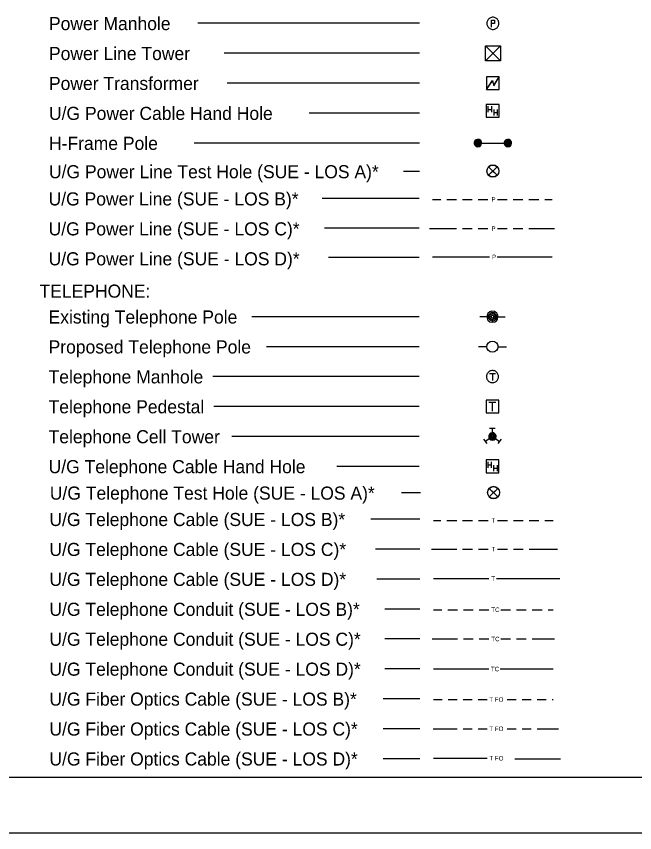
# Model space of a CAD drawing. Extents: x 2040834 to 2047174, y 618431 to 621625.
# Drawn here: x 2046085 to 2046571, y 620341 to 620983 of the extents above; entities that cross this region are included whole.
import ezdxf

# ---------------------------------------------------------------- set-up
doc = ezdxf.new("R2010")
doc.units = 0
for name, color, linetype in [('Default', 7, 'Continuous'), ('Exist Utilities Power Test Hole SUE LOS A CELL', 7, 'Continuous'), ('Exist Utilities Telephone Test Hole SUE LOS A CELL', 7, 'Continuous')]:
    doc.layers.add(name, color=color, linetype=linetype)

msp = doc.modelspace()

# ---------------------------------------------------------------- linework, layer by layer
at = {"layer": 'Default'}
for p, q in [((2046401.89, 620977.7), (2046227.49, 620977.7)), ((2046460.53, 620977.47), (2046458.39, 620977.47)), ((2046460.92, 620979.88), (2046460.92, 620977.85)), ((2046465.49, 620960.07), (2046453.73, 620948.31)), ((2046465.49, 620948.31), (2046453.73, 620960.07)), ((2046401.89, 620954.16), (2046248.08, 620954.16)), ((2046401.89, 620930.62), (2046250.46, 620930.62)), ((2046455.72, 620912.48), (2046455.72, 620907.74)), ((2046458.43, 620912.48), (2046458.43, 620907.74)), ((2046401.89, 620907.07), (2046314.91, 620907.07)), ((2046455.72, 620910.06), (2046458.43, 620910.06)), ((2046460.25, 620909.89), (2046460.25, 620905.15)), ((2046460.25, 620907.48), (2046462.96, 620907.48)), ((2046462.96, 620909.89), (2046462.96, 620905.15)), ((2046401.89, 620883.53), (2046224.51, 620883.53)), ((2046447.81, 620883.53), (2046471.35, 620883.53)), ((2046401.89, 620861.2), (2046389.37, 620861.2)), ((2046401.56, 620839.81), (2046325.15, 620839.81)), ((2046412.17, 620839.23), (2046418.65, 620839.23)), ((2046423.35, 620839.23), (2046431.01, 620839.23)), ((2046435.71, 620839.23), (2046443.37, 620839.23)), ((2046448.07, 620839.23), (2046455.72, 620839.23)), ((2046463.26, 620839.23), (2046470.91, 620839.23)), ((2046475.62, 620839.23), (2046483.27, 620839.23)), ((2046487.98, 620839.23), (2046495.63, 620839.23)), ((2046500.34, 620839.23), (2046506.34, 620839.23)), ((2046401.56, 620816.72), (2046326.96, 620816.72)), ((2046409.79, 620816.27), (2046431.01, 620816.27)), ((2046435.71, 620816.27), (2046443.37, 620816.27)), ((2046448.07, 620816.27), (2046455.72, 620816.27)), ((2046463.26, 620816.27), (2046470.91, 620816.27)), ((2046475.62, 620816.27), (2046483.27, 620816.27)), ((2046487.98, 620816.27), (2046508.02, 620816.27)), ((2046401.56, 620793.63), (2046330.13, 620793.63)), ((2046412.17, 620793.95), (2046457, 620793.95)), ((2046462.89, 620793.95), (2046506.34, 620793.95)), ((2046401.56, 620746.95), (2046269.86, 620746.95)), ((2046454.91, 620746.95), (2046449.26, 620746.95)), ((2046463.6, 620746.95), (2046469.25, 620746.95)), ((2046401.56, 620723.41), (2046281.43, 620723.41)), ((2046454.89, 620723.4), (2046448.27, 620723.4)), ((2046463.71, 620723.4), (2046470.34, 620723.4)), ((2046401.56, 620699.87), (2046239.29, 620699.87)), ((2046461.7, 620702.09), (2046456.85, 620702.09)), ((2046459.26, 620702.09), (2046459.26, 620696.74)), ((2046401.56, 620676.33), (2046240.11, 620676.33)), ((2046456.5, 620679.88), (2046462.01, 620679.88)), ((2046459.26, 620672.78), (2046459.26, 620679.88)), ((2046457.05, 620659.45), (2046461.46, 620659.45)), ((2046459.26, 620655.68), (2046459.26, 620659.45)), ((2046401.56, 620652.79), (2046254.16, 620652.79)), ((2046455.07, 620647.16), (2046452.54, 620650.78)), ((2046456.89, 620651.13), (2046453.81, 620648.97)), ((2046461.63, 620651.13), (2046464.71, 620648.97)), ((2046465.98, 620650.78), (2046463.45, 620647.17)), ((2046401.56, 620629.24), (2046336.78, 620629.24)), ((2046455.65, 620632.81), (2046455.65, 620628.06)), ((2046455.65, 620630.39), (2046458.36, 620630.39)), ((2046458.36, 620632.81), (2046458.36, 620628.06)), ((2046460.18, 620630.22), (2046460.18, 620625.48)), ((2046462.89, 620630.22), (2046462.89, 620625.48)), ((2046460.18, 620627.81), (2046462.89, 620627.81)), ((2046402.53, 620608.44), (2046387.63, 620608.44)), ((2046402.21, 620587.7), (2046363.62, 620587.7)), ((2046412.82, 620586.76), (2046418.73, 620586.76)), ((2046423.44, 620586.76), (2046431.09, 620586.76)), ((2046435.8, 620586.76), (2046443.45, 620586.76)), ((2046448.16, 620586.76), (2046455.81, 620586.76)), ((2046463.34, 620586.76), (2046470.99, 620586.76)), ((2046475.7, 620586.76), (2046483.35, 620586.76)), ((2046488.06, 620586.76), (2046495.71, 620586.76)), ((2046500.42, 620586.76), (2046506.98, 620586.76)), ((2046402.21, 620564.15), (2046367.34, 620564.15)), ((2046411.34, 620564.15), (2046431.09, 620564.15)), ((2046435.8, 620564.15), (2046443.45, 620564.15)), ((2046448.16, 620564.15), (2046455.81, 620564.15)), ((2046463.34, 620564.15), (2046470.99, 620564.15)), ((2046475.7, 620564.15), (2046483.35, 620564.15)), ((2046488.06, 620564.15), (2046510.47, 620564.15)), ((2046402.21, 620540.61), (2046368.24, 620540.61)), ((2046412.82, 620541.02), (2046456.51, 620541.02)), ((2046462.4, 620541.02), (2046512.28, 620541.02)), ((2046402.21, 620517.07), (2046374.59, 620517.07)), ((2046412.82, 620516.57), (2046419.39, 620516.57)), ((2046424.1, 620516.57), (2046431.75, 620516.57)), ((2046436.46, 620516.57), (2046444.11, 620516.57)), ((2046448.82, 620516.57), (2046456.47, 620516.57)), ((2046465.89, 620516.57), (2046473.54, 620516.57)), ((2046478.25, 620516.57), (2046485.9, 620516.57)), ((2046490.61, 620516.57), (2046498.26, 620516.57)), ((2046502.97, 620516.57), (2046506.98, 620516.57)), ((2046402.21, 620493.53), (2046374.59, 620493.53)), ((2046411.7, 620493.53), (2046431.75, 620493.53)), ((2046436.46, 620493.53), (2046444.11, 620493.53)), ((2046448.82, 620493.53), (2046456.47, 620493.53)), ((2046465.89, 620493.53), (2046473.54, 620493.53)), ((2046478.25, 620493.53), (2046485.9, 620493.53)), ((2046490.61, 620493.53), (2046508.11, 620493.53)), ((2046402.21, 620469.99), (2046374.59, 620469.99)), ((2046412.82, 620469.93), (2046456.47, 620469.93)), ((2046465.3, 620469.93), (2046506.98, 620469.93)), ((2046402.21, 620446.44), (2046373.22, 620446.44)), ((2046412.82, 620445.93), (2046419.69, 620445.93)), ((2046424.39, 620445.93), (2046431.46, 620445.93)), ((2046436.17, 620445.93), (2046443.23, 620445.93)), ((2046447.94, 620445.93), (2046455, 620445.93)), ((2046470.89, 620445.93), (2046477.95, 620445.93)), ((2046482.66, 620445.93), (2046489.72, 620445.93)), ((2046494.43, 620445.93), (2046501.49, 620445.93)), ((2046506.2, 620445.93), (2046506.98, 620445.93)), ((2046402.21, 620422.9), (2046373.22, 620422.9)), ((2046412.6, 620422.9), (2046431.46, 620422.9)), ((2046436.17, 620422.9), (2046443.23, 620422.9)), ((2046447.94, 620422.9), (2046455, 620422.9)), ((2046470.89, 620422.9), (2046477.95, 620422.9)), ((2046482.66, 620422.9), (2046489.72, 620422.9)), ((2046494.43, 620422.9), (2046511.28, 620422.9)), ((2046402.21, 620399.36), (2046373.22, 620399.36)), ((2046412.82, 620399.75), (2046455.04, 620399.75)), ((2046476.82, 620399.29), (2046512.87, 620399.29)), ((2045118.13, 620384.96), (2047013.93, 620384.96)), ((2045074.38, 620341.21), (2047057.71, 620341.21))]:
    msp.add_line(p, q, dxfattribs=at)
for points in [[(2046459.58, 620982.48), (2046458.97, 620982.44), (2046458.39, 620982.33), (2046457.82, 620982.13), (2046457.28, 620981.87), (2046456.79, 620981.56), (2046456.33, 620981.18), (2046455.91, 620980.72), (2046455.56, 620980.26), (2046455.26, 620979.73), (2046455.07, 620979.15), (2046454.91, 620978.58), (2046454.84, 620978.01), (2046454.84, 620977.39), (2046454.91, 620976.82), (2046455.07, 620976.21), (2046455.26, 620975.67), (2046455.56, 620975.14), (2046455.91, 620974.68), (2046456.33, 620974.22), (2046456.79, 620973.84), (2046457.28, 620973.53), (2046457.82, 620973.26), (2046458.39, 620973.07), (2046459, 620972.96), (2046459.58, 620972.92), (2046460.19, 620972.96), (2046460.76, 620973.07), (2046461.34, 620973.26), (2046461.87, 620973.53), (2046462.37, 620973.84), (2046462.83, 620974.22), (2046463.25, 620974.68), (2046463.59, 620975.14), (2046463.9, 620975.67), (2046464.09, 620976.25), (2046464.24, 620976.82), (2046464.32, 620977.39), (2046464.32, 620978.01), (2046464.24, 620978.58), (2046464.09, 620979.19), (2046463.9, 620979.73), (2046463.59, 620980.26), (2046463.25, 620980.72), (2046462.83, 620981.18), (2046462.37, 620981.56), (2046461.87, 620981.87), (2046461.34, 620982.13), (2046460.76, 620982.33), (2046460.15, 620982.44), (2046459.58, 620982.48)], [(2046458.39, 620974.64), (2046458.39, 620977.47), (2046458.39, 620980.26), (2046460.53, 620980.26)], [(2046460.53, 620980.26), (2046460.69, 620980.22), (2046460.8, 620980.15), (2046460.88, 620980.03), (2046460.92, 620979.88)], [(2046460.92, 620977.85), (2046460.88, 620977.7), (2046460.8, 620977.58), (2046460.69, 620977.51), (2046460.53, 620977.47)], [(2046465.49, 620948.31), (2046453.73, 620948.31), (2046453.73, 620960.07), (2046465.49, 620960.07), (2046465.49, 620948.31), (2046453.73, 620948.31), (2046453.73, 620960.07), (2046465.49, 620960.07), (2046465.49, 620948.31)], [(2046454.67, 620925.71), (2046459.3, 620932.37), (2046460.43, 620928.75), (2046464.48, 620935.52)], [(2046454.67, 620925.71), (2046459.34, 620932.64), (2046460.39, 620928.47), (2046464.48, 620935.52)], [(2046454.67, 620925.71), (2046464.48, 620925.71), (2046464.48, 620935.52), (2046454.67, 620935.52), (2046454.67, 620925.71)], [(2046454.27, 620903.85), (2046464.4, 620903.85), (2046464.4, 620913.98), (2046454.27, 620913.98), (2046454.27, 620903.85)], [(2046449.95, 620883.53), (2046449.89, 620884.05), (2046449.72, 620884.52), (2046449.43, 620884.92), (2046449.08, 620885.27), (2046448.68, 620885.5), (2046448.15, 620885.62), (2046447.69, 620885.68), (2046447.17, 620885.56), (2046446.71, 620885.39), (2046446.36, 620885.1), (2046446.01, 620884.69), (2046445.78, 620884.28), (2046445.66, 620883.76), (2046445.66, 620883.3), (2046445.78, 620882.78), (2046446.01, 620882.37), (2046446.36, 620881.97), (2046446.71, 620881.68), (2046447.17, 620881.5), (2046447.69, 620881.39), (2046448.15, 620881.45), (2046448.68, 620881.56), (2046449.08, 620881.8), (2046449.43, 620882.14), (2046449.72, 620882.55), (2046449.89, 620883.01), (2046449.95, 620883.53)], [(2046449.25, 620883.53), (2046449.2, 620883.94), (2046449.02, 620884.34), (2046448.73, 620884.63), (2046448.39, 620884.86), (2046448.04, 620884.98), (2046447.57, 620884.98), (2046447.23, 620884.86), (2046446.88, 620884.63), (2046446.59, 620884.34), (2046446.42, 620883.94), (2046446.36, 620883.53), (2046446.42, 620883.13), (2046446.59, 620882.72), (2046446.88, 620882.43), (2046447.23, 620882.2), (2046447.57, 620882.08), (2046448.04, 620882.08), (2046448.39, 620882.2), (2046448.73, 620882.43), (2046449.02, 620882.72), (2046449.2, 620883.13), (2046449.25, 620883.53)], [(2046448.5, 620883.53), (2046448.44, 620883.82), (2046448.27, 620884.05), (2046448.04, 620884.17), (2046447.75, 620884.23), (2046447.46, 620884.11), (2046447.23, 620883.94), (2046447.11, 620883.65), (2046447.11, 620883.42), (2046447.23, 620883.13), (2046447.46, 620882.95), (2046447.75, 620882.84), (2046448.04, 620882.89), (2046448.27, 620883.01), (2046448.44, 620883.24), (2046448.5, 620883.53)], [(2046473.49, 620883.53), (2046473.43, 620884.05), (2046473.26, 620884.52), (2046472.97, 620884.92), (2046472.62, 620885.27), (2046472.22, 620885.5), (2046471.7, 620885.62), (2046471.23, 620885.68), (2046470.71, 620885.56), (2046470.25, 620885.39), (2046469.9, 620885.1), (2046469.55, 620884.69), (2046469.32, 620884.28), (2046469.2, 620883.76), (2046469.2, 620883.3), (2046469.32, 620882.78), (2046469.55, 620882.37), (2046469.9, 620881.97), (2046470.25, 620881.68), (2046470.71, 620881.5), (2046471.23, 620881.39), (2046471.7, 620881.45), (2046472.22, 620881.56), (2046472.62, 620881.8), (2046472.97, 620882.14), (2046473.26, 620882.55), (2046473.43, 620883.01), (2046473.49, 620883.53)], [(2046472.8, 620883.53), (2046472.74, 620883.94), (2046472.56, 620884.34), (2046472.28, 620884.63), (2046471.93, 620884.86), (2046471.58, 620884.98), (2046471.12, 620884.98), (2046470.77, 620884.86), (2046470.42, 620884.63), (2046470.13, 620884.34), (2046469.96, 620883.94), (2046469.9, 620883.53), (2046469.96, 620883.13), (2046470.13, 620882.72), (2046470.42, 620882.43), (2046470.77, 620882.2), (2046471.12, 620882.08), (2046471.58, 620882.08), (2046471.93, 620882.2), (2046472.28, 620882.43), (2046472.56, 620882.72), (2046472.74, 620883.13), (2046472.8, 620883.53)], [(2046472.04, 620883.53), (2046471.99, 620883.82), (2046471.81, 620884.05), (2046471.58, 620884.17), (2046471.29, 620884.23), (2046471, 620884.11), (2046470.77, 620883.94), (2046470.65, 620883.65), (2046470.65, 620883.42), (2046470.77, 620883.13), (2046471, 620882.95), (2046471.29, 620882.84), (2046471.58, 620882.89), (2046471.81, 620883.01), (2046471.99, 620883.24), (2046472.04, 620883.53)], [(2046462.47, 620746.95), (2046462.38, 620747.74), (2046462.12, 620748.43), (2046461.69, 620749.04), (2046461.17, 620749.56), (2046460.56, 620749.91), (2046459.78, 620750.08), (2046459.08, 620750.17), (2046458.3, 620750), (2046457.6, 620749.73), (2046457.08, 620749.3), (2046456.56, 620748.69), (2046456.21, 620748.08), (2046456.04, 620747.3), (2046456.04, 620746.61), (2046456.21, 620745.83), (2046456.56, 620745.22), (2046457.08, 620744.61), (2046457.6, 620744.17), (2046458.3, 620743.91), (2046459.08, 620743.74), (2046459.78, 620743.83), (2046460.56, 620744), (2046461.17, 620744.35), (2046461.69, 620744.87), (2046462.12, 620745.48), (2046462.38, 620746.17), (2046462.47, 620746.95)], [(2046461.43, 620746.95), (2046461.34, 620747.56), (2046461.08, 620748.17), (2046460.65, 620748.61), (2046460.13, 620748.95), (2046459.6, 620749.13), (2046458.91, 620749.13), (2046458.39, 620748.95), (2046457.87, 620748.61), (2046457.43, 620748.17), (2046457.17, 620747.56), (2046457.08, 620746.95), (2046457.17, 620746.35), (2046457.43, 620745.74), (2046457.87, 620745.3), (2046458.39, 620744.96), (2046458.91, 620744.78), (2046459.6, 620744.78), (2046460.13, 620744.96), (2046460.65, 620745.3), (2046461.08, 620745.74), (2046461.34, 620746.35), (2046461.43, 620746.95)], [(2046460.3, 620746.95), (2046460.21, 620747.39), (2046459.95, 620747.74), (2046459.6, 620747.91), (2046459.17, 620748), (2046458.74, 620747.82), (2046458.39, 620747.56), (2046458.21, 620747.13), (2046458.21, 620746.78), (2046458.39, 620746.35), (2046458.74, 620746.08), (2046459.17, 620745.91), (2046459.6, 620746), (2046459.95, 620746.17), (2046460.21, 620746.52), (2046460.3, 620746.95)], [(2046459.26, 620704.65), (2046458.64, 620704.61), (2046458.07, 620704.5), (2046457.5, 620704.31), (2046456.96, 620704.04), (2046456.47, 620703.73), (2046456.01, 620703.35), (2046455.58, 620702.89), (2046455.24, 620702.43), (2046454.94, 620701.9), (2046454.74, 620701.32), (2046454.59, 620700.75), (2046454.52, 620700.18), (2046454.52, 620699.56), (2046454.59, 620698.99), (2046454.74, 620698.38), (2046454.94, 620697.84), (2046455.24, 620697.31), (2046455.58, 620696.85), (2046456.01, 620696.39), (2046456.47, 620696.01), (2046456.96, 620695.7), (2046457.5, 620695.44), (2046458.07, 620695.24), (2046458.68, 620695.13), (2046459.26, 620695.09), (2046459.87, 620695.13), (2046460.44, 620695.24), (2046461.02, 620695.44), (2046461.55, 620695.7), (2046462.05, 620696.01), (2046462.51, 620696.39), (2046462.93, 620696.85), (2046463.27, 620697.31), (2046463.58, 620697.84), (2046463.77, 620698.42), (2046463.92, 620698.99), (2046464, 620699.56), (2046464, 620700.18), (2046463.92, 620700.75), (2046463.77, 620701.36), (2046463.58, 620701.9), (2046463.27, 620702.43), (2046462.93, 620702.89), (2046462.51, 620703.35), (2046462.05, 620703.73), (2046461.55, 620704.04), (2046461.02, 620704.31), (2046460.44, 620704.5), (2046459.83, 620704.61), (2046459.26, 620704.65)], [(2046454.3, 620671.37), (2046464.21, 620671.37), (2046464.21, 620681.28), (2046454.3, 620681.28), (2046454.3, 620671.37)], [(2046461.4, 620652.79), (2046461.34, 620653.31), (2046461.17, 620653.77), (2046460.88, 620654.18), (2046460.53, 620654.52), (2046460.13, 620654.76), (2046459.6, 620654.87), (2046459.14, 620654.93), (2046458.62, 620654.81), (2046458.16, 620654.64), (2046457.81, 620654.35), (2046457.46, 620653.95), (2046457.23, 620653.54), (2046457.11, 620653.02), (2046457.11, 620652.56), (2046457.23, 620652.03), (2046457.46, 620651.63), (2046457.81, 620651.22), (2046458.16, 620650.93), (2046458.62, 620650.76), (2046459.14, 620650.64), (2046459.6, 620650.7), (2046460.13, 620650.82), (2046460.53, 620651.05), (2046460.88, 620651.4), (2046461.17, 620651.8), (2046461.34, 620652.27), (2046461.4, 620652.79)], [(2046460.7, 620652.79), (2046460.65, 620653.19), (2046460.47, 620653.6), (2046460.18, 620653.89), (2046459.84, 620654.12), (2046459.49, 620654.23), (2046459.02, 620654.23), (2046458.68, 620654.12), (2046458.33, 620653.89), (2046458.04, 620653.6), (2046457.87, 620653.19), (2046457.81, 620652.79), (2046457.87, 620652.38), (2046458.04, 620651.98), (2046458.33, 620651.69), (2046458.68, 620651.45), (2046459.02, 620651.34), (2046459.49, 620651.34), (2046459.84, 620651.45), (2046460.18, 620651.69), (2046460.47, 620651.98), (2046460.65, 620652.38), (2046460.7, 620652.79)], [(2046459.95, 620652.79), (2046459.89, 620653.08), (2046459.72, 620653.31), (2046459.49, 620653.42), (2046459.2, 620653.48), (2046458.91, 620653.37), (2046458.68, 620653.19), (2046458.56, 620652.9), (2046458.56, 620652.67), (2046458.68, 620652.38), (2046458.91, 620652.21), (2046459.2, 620652.09), (2046459.49, 620652.15), (2046459.72, 620652.27), (2046459.89, 620652.5), (2046459.95, 620652.79)], [(2046454.19, 620624.18), (2046464.32, 620624.18), (2046464.32, 620634.31), (2046454.19, 620634.31), (2046454.19, 620624.18)]]:
    msp.add_lwpolyline(points, dxfattribs=at)
for points in [[(2046447.81, 620880.63), (2046449.02, 620880.87), (2046449.83, 620881.45), (2046450.47, 620882.26), (2046450.7, 620883.36), (2046450.59, 620884.4), (2046450.01, 620885.44), (2046448.85, 620886.31), (2046447.52, 620886.43), (2046446.36, 620886.08), (2046445.43, 620885.27), (2046444.97, 620884.17), (2046444.97, 620882.89), (2046445.43, 620881.8), (2046446.47, 620880.92)], [(2046471.35, 620880.63), (2046472.56, 620880.87), (2046473.38, 620881.45), (2046474.01, 620882.26), (2046474.25, 620883.36), (2046474.13, 620884.4), (2046473.55, 620885.44), (2046472.39, 620886.31), (2046471.06, 620886.43), (2046469.9, 620886.08), (2046468.97, 620885.27), (2046468.51, 620884.17), (2046468.51, 620882.89), (2046468.97, 620881.8), (2046470.02, 620880.92)], [(2046459.26, 620742.61), (2046461.08, 620742.96), (2046462.3, 620743.83), (2046463.25, 620745.04), (2046463.6, 620746.69), (2046463.43, 620748.26), (2046462.56, 620749.82), (2046460.82, 620751.12), (2046458.82, 620751.3), (2046457.08, 620750.78), (2046455.69, 620749.56), (2046455, 620747.91), (2046455, 620746), (2046455.69, 620744.35), (2046457.26, 620743.04)], [(2046459.26, 620649.89), (2046460.47, 620650.12), (2046461.28, 620650.7), (2046461.92, 620651.51), (2046462.15, 620652.61), (2046462.04, 620653.66), (2046461.46, 620654.7), (2046460.3, 620655.57), (2046458.97, 620655.68), (2046457.81, 620655.34), (2046456.88, 620654.52), (2046456.42, 620653.42), (2046456.42, 620652.15), (2046456.88, 620651.05), (2046457.92, 620650.18)]]:
    msp.add_lwpolyline(points, close=True, dxfattribs=at)
msp.add_circle((2046459.26, 620723.41), 4.41, dxfattribs=at)
at = {"layer": 'Exist Utilities Power Test Hole SUE LOS A CELL'}
for points in [[(2046462.88, 620864.89), (2046456.22, 620858.23), (2046459.55, 620861.56), (2046456.22, 620864.89), (2046462.88, 620858.23)], [(2046456.22, 620864.89), (2046459.55, 620861.56), (2046462.88, 620864.89)], [(2046462.88, 620858.23), (2046459.55, 620861.56), (2046456.22, 620858.23)]]:
    msp.add_lwpolyline(points, dxfattribs=at)
msp.add_circle((2046459.55, 620861.56), 4.7, dxfattribs=at)
for start, end in [(45, 135), (225, 315)]:
    msp.add_arc((2046459.55, 620861.56), 4.7, start, end, dxfattribs=at)
at = {"layer": 'Exist Utilities Telephone Test Hole SUE LOS A CELL'}
for points in [[(2046463.43, 620611.99), (2046456.78, 620605.33), (2046460.11, 620608.66), (2046456.78, 620611.99), (2046463.43, 620605.33)], [(2046456.78, 620611.99), (2046460.11, 620608.66), (2046463.43, 620611.99)], [(2046463.43, 620605.33), (2046460.11, 620608.66), (2046456.78, 620605.33)]]:
    msp.add_lwpolyline(points, dxfattribs=at)
msp.add_circle((2046460.11, 620608.66), 4.7, dxfattribs=at)
for start, end in [(45, 135), (225, 315)]:
    msp.add_arc((2046460.11, 620608.66), 4.7, start, end, dxfattribs=at)

# ---------------------------------------------------------------- texts
at = {"layer": 'Default'}
for s, height, p in [('Power Manhole', 10.2996, (2046110.29, 620972.36)), ('Power Line Tower', 10.2996, (2046110.29, 620948.83)), ('Power Transformer', 10.2996, (2046110.27, 620925.29)), ('U/G Power Cable Hand Hole', 10.2996, (2046110.3, 620901.73)), ('H-Frame Pole', 10.2996, (2046110.3, 620878.19)), ('U/G Power Line Test Hole (SUE - LOS A)*', 10.2996, (2046110.3, 620855.85)), ('U/G Power Line (SUE - LOS B)*', 10.2996, (2046109.98, 620834.47)), ('P', 3.53, (2046458.43, 620837.47)), ('U/G Power Line (SUE - LOS C)*', 10.2996, (2046110.01, 620810.91)), ('P', 3.53, (2046458.43, 620814.5)), ('U/G Power Line (SUE - LOS D)*', 10.2996, (2046110.04, 620787.36)), ('P', 3.53, (2046458.89, 620792.19)), ('TELEPHONE:', 10.3, (2046102.85, 620761.96)), ('Existing Telephone Pole', 10.2996, (2046109.98, 620741.61)), ('Proposed Telephone Pole', 10.2996, (2046109.98, 620718.07)), ('Telephone Manhole', 10.2996, (2046109.98, 620694.53)), ('Telephone Pedestal', 10.2996, (2046109.98, 620670.99)), ('Telephone Cell Tower', 10.2996, (2046110, 620647.45)), ('U/G Telephone Cable Hand Hole', 10.2996, (2046110, 620623.9)), ('U/G Telephone Test Hole (SUE - LOS A)*', 10.2996, (2046110.96, 620603.1)), ('U/G Telephone Cable (SUE - LOS B)*', 10.2996, (2046110.64, 620582.35)), ('T', 3.53, (2046458.46, 620584.99)), ('U/G Telephone Cable (SUE - LOS C)*', 10.2996, (2046110.64, 620558.81)), ('T', 3.53, (2046458.46, 620562.39)), ('U/G Telephone Cable (SUE - LOS D)*', 10.2996, (2046110.64, 620535.27)), ('T', 3.53, (2046458.34, 620539.26)), ('U/G Telephone Conduit (SUE - LOS B)*', 10.2996, (2046110.64, 620511.73)), ('TC', 3.531, (2046458.35, 620514.8)), ('U/G Telephone Conduit (SUE - LOS C)*', 10.2996, (2046110.64, 620488.19)), ('TC', 3.531, (2046458.35, 620491.76)), ('U/G Telephone Conduit (SUE - LOS D)*', 10.2996, (2046110.64, 620464.65)), ('TC', 3.531, (2046458.06, 620468.16)), ('U/G Fiber Optics Cable (SUE - LOS B)*', 10.2996, (2046110.64, 620441.1)), ('T FO', 3.531, (2046456.77, 620444.17)), ('U/G Fiber Optics Cable (SUE - LOS C)*', 10.2996, (2046110.64, 620417.56)), ('T FO', 3.531, (2046456.77, 620421.14)), ('U/G Fiber Optics Cable (SUE - LOS D)*', 10.2996, (2046110.64, 620394.02)), ('T FO', 3.531, (2046456.81, 620397.98))]:
    msp.add_text(s, height=height, dxfattribs=at).set_placement(p)

doc.saveas('drawing.dxf')
